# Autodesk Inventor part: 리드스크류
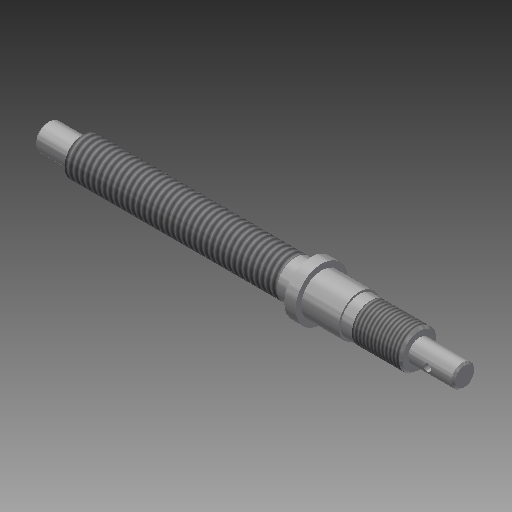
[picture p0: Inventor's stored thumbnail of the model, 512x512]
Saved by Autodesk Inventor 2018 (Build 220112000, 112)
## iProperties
Created: 2020-03
Part Number: 리드스크류
Material: 강철, 연강
Document SubType Name: Modeling
Designer: mduedu
Density: 7.86 g/cm^3
Appearance: 강철
Mass: 63.7787 g
Surface Area: 36.2713 cm^2
Volume: 8.11434 cm^3
Author: mduedu
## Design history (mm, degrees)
sketch "스케치1"
  geometry: L1 (0, 0)-(9, 0); L2 (9, 0)-(9, 3.5); L3 (9, 3.5)-(0, 3.5); L4 (0, 3.5)-(0, 0); L5 (9, 0)-(70, 0); L6 (70, 0)-(70, 5); L7 (70, 5)-(9, 5); L8 (9, 5)-(9, 0); L9 (70, 0)-(73, 0); L10 (73, 0)-(73, 7); L11 (73, 7)-(70, 7); L12 (70, 7)-(70, 0); L13 (73, 0)-(83, 0); L14 (83, 0)-(83, 5.5); L15 (83, 5.5)-(73, 5.5); L16 (73, 5.5)-(73, 0); L17 (83, 0)-(99, 0); L18 (99, 0)-(99, 5); L19 (99, 5)-(83, 5); L20 (83, 5)-(83, 0); L21 (99, 0)-(111, 0); L22 (111, 0)-(111, 3); L23 (111, 3)-(99, 3); L24 (99, 3)-(99, 0)
  constraints: 48 end point, 12 parallel, 6 horizontal, 6 perpendicular
  dimensions: "d0" = 61 distance of L6.end L7.end; "d2" = 9 distance of L2.end L3.end; "d3" = 3 distance of L10.end L11.end; "d4" = 10 distance of L14.end L15.end; "d5" = 16 distance of L18.end L19.end; "d6" = 12 distance of L22.end L23.end; "d7" = 7 diameter of L3 L1; "d8" = 10 diameter of L7 L5; "d9" = 14 diameter of L11 L9; "d10" = 11 diameter of L15 L13; "d11" = 10 diameter of L19 L17; "d12" = 6 diameter of L23 L21
revolve "회전1" sketch "스케치1" stored, may be unused: angle "d13" = 90 deg
feature "스레드1" dims "d14" = 57, "d15" = 0
feature "스레드2" dims "d16" = 13, "d17" = 0
chamfer "모따기1" distance "d18" = 0.5; stored, may be unused: second distance "d19" = 2, angle "d20" = 45 deg
sketch "스케치2"
  geometry: L1 (111, 2.5)-(111, -2.5) reference; C1 r 1 at (104, 0); 1 further point
  constraints: 1 centre point, 1 horizontal alignment
  dimensions: "d21" = 2 diameter of C1; "d22" = 7 distance from line of C1.centre L1
extrude "돌출1" cut sketch "스케치2" extent not by distance; stored distance "d23" = 10; taper "d24" = 0 deg
node "솔리드1"
